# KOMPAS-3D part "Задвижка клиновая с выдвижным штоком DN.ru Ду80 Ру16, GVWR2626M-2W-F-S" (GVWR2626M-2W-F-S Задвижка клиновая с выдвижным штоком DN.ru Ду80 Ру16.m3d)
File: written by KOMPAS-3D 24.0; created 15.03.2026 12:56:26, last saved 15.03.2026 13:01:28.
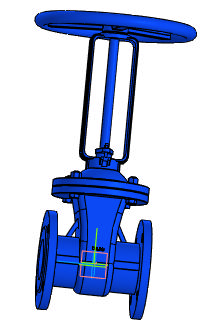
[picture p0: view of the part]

Document properties: Автор: R2D2; Полное имя файла: E:\Работа\Зайцев\GVWR2626M-2W-F-S Задвижка клиновая с выдвижным штоком DN.ru Ду50-300 Ру16\DN80\GVWR2626M-2W-F-S Задвижка клиновая с выдвижным штоком DN.ru Ду80 Ру16.m3d

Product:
- Part/product: Задвижка клиновая с выдвижным штоком DN.ru Ду80 Ру16  | designation GVWR2626M-2W-F-S
    Масса: 24
    Раздел спецификации: Прочие изделия
    Примечание: D040-10501

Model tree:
1. Операция без истории:1

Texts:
  GVWR2626M-2W-F-S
